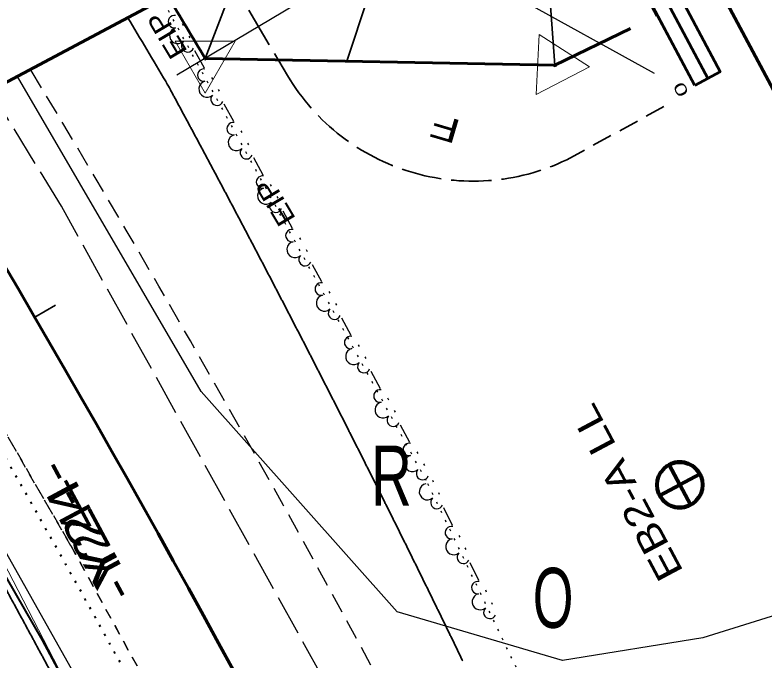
# Model space of a CAD drawing. Extents: x 2402199 to 2404507, y 568050 to 571478.
# Drawn here: x 2402420.4 to 2402576.7, y 571079.7 to 571214.3 of the extents above; entities that cross this region are included whole.
import ezdxf
from ezdxf.enums import TextEntityAlignment as Align

# ---------------------------------------------------------------- set-up
doc = ezdxf.new("R2010")
doc.units = 0
doc.header["$LTSCALE"] = 1.4
doc.header["$PDMODE"] = 32
doc.header["$PDSIZE"] = 0.7
for name, pattern in [('DOTTED', [1.5, 0.3, -1.2]), ('LONG_DASHED', [7.5, 6, -1.5]), ('MEDIUM_DASHED', [4.5, 3, -1.5]), ('SHORT_DASHED', [2.7, 1.5, -1.2])]:
    doc.linetypes.add(name, pattern=pattern)
for name, color, linetype, lineweight in [('1', 7, 'Continuous', 35), ('11', 7, 'Continuous', 25), ('15', 7, 'DOTTED', 40), ('17', 7, 'MEDIUM_DASHED', 35), ('18', 7, 'SHORT_DASHED', 25), ('19', 7, 'Continuous', 35), ('21', 7, 'Continuous', 40), ('27', 7, 'Continuous', 80), ('28', 7, 'Continuous', 25), ('3', 7, 'Continuous', 25), ('4', 7, 'Continuous', 13), ('52', 7, 'Continuous', 25), ('6', 7, 'Continuous', 35), ('62', 7, 'Continuous', 60), ('63', 7, 'Continuous', 35), ('9', 7, 'Continuous', 13)]:
    doc.layers.add(name, color=color, linetype=linetype, lineweight=lineweight)
doc.layers.add('14', color=7, linetype='Continuous')
doc.layers.add('23', color=7, linetype='Continuous')

msp = doc.modelspace()

# ---------------------------------------------------------------- linework, layer by layer
at = {"layer": '1'}
msp.add_arc((2399929.798, 569697.989), 2935.633, 30.78279, 31.08702, dxfattribs=at)
for points in [[(2402483.513, 571140.326), (2402483.095, 571141.14), (2402482.672, 571141.963), (2402482.255, 571142.777), (2402481.837, 571143.591), (2402481.418, 571144.405), (2402480.999, 571145.218), (2402480.581, 571146.032), (2402480.161, 571146.845), (2402479.742, 571147.659), (2402479.322, 571148.471), (2402478.902, 571149.285), (2402478.482, 571150.098), (2402478.056, 571150.92), (2402477.635, 571151.732), (2402477.215, 571152.544), (2402476.794, 571153.357), (2402476.372, 571154.169), (2402475.95, 571154.981), (2402475.528, 571155.794), (2402475.106, 571156.606), (2402474.683, 571157.417), (2402474.26, 571158.229), (2402473.837, 571159.041), (2402473.413, 571159.853), (2402472.985, 571160.673), (2402472.561, 571161.484), (2402472.137, 571162.295), (2402471.713, 571163.106), (2402471.288, 571163.917), (2402470.863, 571164.728), (2402470.438, 571165.539), (2402470.012, 571166.349), (2402469.587, 571167.159), (2402469.161, 571167.97), (2402468.735, 571168.78), (2402468.303, 571169.599), (2402467.876, 571170.409), (2402467.45, 571171.218), (2402467.022, 571172.028), (2402466.595, 571172.837), (2402466.167, 571173.647), (2402465.739, 571174.456), (2402465.311, 571175.265), (2402464.882, 571176.074), (2402464.453, 571176.883), (2402464.024, 571177.693), (2402463.59, 571178.51), (2402463.16, 571179.318), (2402462.731, 571180.126), (2402462.3, 571180.935), (2402461.87, 571181.743), (2402461.439, 571182.551), (2402461.009, 571183.358), (2402460.578, 571184.167), (2402460.146, 571184.974), (2402459.714, 571185.782), (2402459.282, 571186.59), (2402458.845, 571187.405), (2402458.413, 571188.213), (2402457.98, 571189.02), (2402457.547, 571189.826), (2402457.114, 571190.633), (2402456.681, 571191.44), (2402456.247, 571192.247), (2402455.813, 571193.053), (2402455.379, 571193.859), (2402454.945, 571194.666), (2402454.509, 571195.472), (2402454.07, 571196.286), (2402453.635, 571197.092), (2402453.199, 571197.897), (2402452.763, 571198.703), (2402451.891, 571200.313)], [(2402513.706, 571079.688), (2402513.308, 571080.51), (2402512.909, 571081.333), (2402512.511, 571082.156), (2402512.112, 571082.978), (2402511.713, 571083.801), (2402511.314, 571084.623), (2402510.914, 571085.446), (2402510.514, 571086.268), (2402510.113, 571087.091), (2402509.708, 571087.921), (2402509.308, 571088.743), (2402508.907, 571089.564), (2402508.505, 571090.386), (2402508.104, 571091.207), (2402507.703, 571092.029), (2402507.3, 571092.85), (2402506.898, 571093.671), (2402506.496, 571094.492), (2402506.093, 571095.313), (2402505.689, 571096.134), (2402505.281, 571096.964), (2402504.878, 571097.784), (2402504.474, 571098.604), (2402504.07, 571099.424), (2402503.666, 571100.245), (2402503.261, 571101.064), (2402502.856, 571101.884), (2402502.451, 571102.704), (2402502.046, 571103.524), (2402501.64, 571104.344), (2402501.234, 571105.164), (2402500.823, 571105.992), (2402500.416, 571106.811), (2402500.01, 571107.63), (2402499.603, 571108.449), (2402499.195, 571109.268), (2402498.788, 571110.086), (2402498.38, 571110.905), (2402497.972, 571111.724), (2402497.564, 571112.542), (2402497.155, 571113.361), (2402496.746, 571114.179), (2402496.333, 571115.006), (2402495.924, 571115.824), (2402495.514, 571116.642), (2402495.104, 571117.459), (2402494.694, 571118.277), (2402494.284, 571119.094), (2402493.873, 571119.912), (2402493.462, 571120.729), (2402493.051, 571121.547), (2402492.64, 571122.363), (2402492.228, 571123.181), (2402491.811, 571124.006), (2402491.399, 571124.823), (2402490.986, 571125.639), (2402490.574, 571126.456), (2402490.161, 571127.272), (2402489.748, 571128.088), (2402489.334, 571128.904), (2402488.92, 571129.72), (2402488.506, 571130.536), (2402488.092, 571131.351), (2402487.677, 571132.167), (2402487.257, 571132.992), (2402486.842, 571133.807), (2402486.427, 571134.622), (2402486.012, 571135.437), (2402485.596, 571136.252), (2402485.18, 571137.067), (2402484.763, 571137.882), (2402484.347, 571138.696), (2402483.93, 571139.511), (2402483.513, 571140.325)], [(2402513.706, 571079.688), (2402513.308, 571080.51), (2402512.909, 571081.333), (2402512.511, 571082.156), (2402512.112, 571082.978), (2402511.713, 571083.801), (2402511.314, 571084.623), (2402510.914, 571085.446), (2402510.514, 571086.268), (2402510.113, 571087.091), (2402509.708, 571087.921), (2402509.308, 571088.743), (2402508.907, 571089.564), (2402508.505, 571090.386), (2402508.104, 571091.207), (2402507.703, 571092.029), (2402507.3, 571092.85), (2402506.898, 571093.671), (2402506.496, 571094.492), (2402506.093, 571095.313), (2402505.689, 571096.134), (2402505.281, 571096.964), (2402504.878, 571097.784), (2402504.474, 571098.604), (2402504.07, 571099.424), (2402503.666, 571100.245), (2402503.261, 571101.064), (2402502.856, 571101.884), (2402502.451, 571102.704), (2402502.046, 571103.524), (2402501.64, 571104.344), (2402501.234, 571105.164), (2402500.823, 571105.992), (2402500.416, 571106.811), (2402500.01, 571107.63), (2402499.603, 571108.449), (2402499.195, 571109.268), (2402498.788, 571110.086), (2402498.38, 571110.905), (2402497.972, 571111.724), (2402497.564, 571112.542), (2402497.155, 571113.361), (2402496.746, 571114.179), (2402496.333, 571115.006), (2402495.924, 571115.824), (2402495.514, 571116.642), (2402495.104, 571117.459), (2402494.694, 571118.277), (2402494.284, 571119.094), (2402493.873, 571119.912), (2402493.462, 571120.729), (2402493.051, 571121.547), (2402492.64, 571122.363), (2402492.228, 571123.181), (2402491.811, 571124.006), (2402491.399, 571124.823), (2402490.986, 571125.639), (2402490.574, 571126.456), (2402490.161, 571127.272), (2402489.748, 571128.088), (2402489.334, 571128.904), (2402488.92, 571129.72), (2402488.506, 571130.536), (2402488.092, 571131.351), (2402487.677, 571132.167), (2402487.257, 571132.992), (2402486.842, 571133.807), (2402486.427, 571134.622), (2402486.012, 571135.437), (2402485.596, 571136.252), (2402485.18, 571137.067), (2402484.763, 571137.882), (2402484.347, 571138.696), (2402483.93, 571139.511), (2402483.513, 571140.325)], [(2402445.746, 571043.492), (2402445.335, 571044.281), (2402444.925, 571045.069), (2402444.513, 571045.858), (2402444.102, 571046.647), (2402443.691, 571047.436), (2402443.279, 571048.224), (2402442.867, 571049.012), (2402442.454, 571049.8), (2402442.041, 571050.588), (2402441.624, 571051.385), (2402441.211, 571052.172), (2402440.797, 571052.96), (2402440.384, 571053.748), (2402439.97, 571054.535), (2402439.556, 571055.322), (2402439.142, 571056.109), (2402438.727, 571056.897), (2402438.312, 571057.684), (2402437.897, 571058.47), (2402437.482, 571059.257), (2402437.062, 571060.052), (2402436.646, 571060.838), (2402436.23, 571061.624), (2402435.813, 571062.41), (2402435.397, 571063.196), (2402434.98, 571063.983), (2402434.563, 571064.768), (2402434.146, 571065.554), (2402433.728, 571066.339), (2402433.311, 571067.125), (2402432.893, 571067.91), (2402432.47, 571068.703), (2402432.051, 571069.488), (2402431.632, 571070.273), (2402431.213, 571071.058), (2402430.794, 571071.843), (2402430.374, 571072.627), (2402429.954, 571073.411), (2402429.535, 571074.196), (2402429.114, 571074.98), (2402428.694, 571075.764), (2402428.273, 571076.547), (2402427.848, 571077.34), (2402427.426, 571078.123), (2402427.005, 571078.906), (2402426.583, 571079.69), (2402426.161, 571080.473), (2402425.739, 571081.256), (2402425.316, 571082.039), (2402424.894, 571082.822), (2402424.471, 571083.604), (2402424.047, 571084.387), (2402423.624, 571085.169), (2402423.195, 571085.96), (2402422.771, 571086.742), (2402422.347, 571087.524), (2402421.923, 571088.306), (2402421.498, 571089.088), (2402421.073, 571089.87), (2402420.648, 571090.651), (2402420.223, 571091.432), (2402419.797, 571092.214), (2402419.371, 571092.995), (2402418.945, 571093.775), (2402418.514, 571094.565), (2402418.087, 571095.346), (2402417.66, 571096.126), (2402417.233, 571096.907), (2402416.806, 571097.687), (2402416.378, 571098.467), (2402415.95, 571099.247), (2402415.522, 571100.027), (2402415.094, 571100.807), (2402414.665, 571101.587)]]:
    msp.add_spline(points, degree=3, dxfattribs=at)
at = {"layer": '11', "linetype": 'DOTTED'}
for p, q in [((2402506.107, 571117.3), (2402451.036, 571217.605)), ((2402547.635, 571031.07), (2402506.107, 571117.3))]:
    msp.add_line(p, q, dxfattribs=at)
at = {"layer": '11'}
for p, q in [((2402455.475, 571212.078), (2402455.277, 571212.438)), ((2402456.856, 571209.56), (2402456.66, 571209.919)), ((2402459.853, 571203.252), (2402457.879, 571206.847)), ((2402461.593, 571200.932), (2402461.396, 571201.292)), ((2402462.975, 571198.418), (2402462.777, 571198.777)), ((2402465.971, 571192.108), (2402463.997, 571195.703)), ((2402467.712, 571189.789), (2402467.514, 571190.149)), ((2402469.094, 571187.273), (2402468.896, 571187.633)), ((2402472.089, 571180.964), (2402470.116, 571184.559)), ((2402473.831, 571178.645), (2402473.633, 571179.005)), ((2402475.213, 571176.127), (2402475.016, 571176.487)), ((2402478.208, 571169.821), (2402476.235, 571173.414)), ((2402479.949, 571167.501), (2402479.752, 571167.86)), ((2402481.33, 571164.986), (2402481.132, 571165.345)), ((2402484.327, 571158.676), (2402482.353, 571162.271)), ((2402486.067, 571156.358), (2402485.869, 571156.718)), ((2402487.448, 571153.842), (2402487.251, 571154.201)), ((2402490.445, 571147.532), (2402488.471, 571151.127)), ((2402492.185, 571145.214), (2402491.988, 571145.574)), ((2402493.567, 571142.696), (2402493.371, 571143.056)), ((2402496.564, 571136.388), (2402494.59, 571139.983)), ((2402498.304, 571134.068), (2402498.107, 571134.427)), ((2402499.685, 571131.554), (2402499.488, 571131.913)), ((2402502.682, 571125.244), (2402500.708, 571128.839)), ((2402504.422, 571122.926), (2402504.224, 571123.285)), ((2402505.804, 571120.41), (2402505.606, 571120.769)), ((2402507.64, 571116.955), (2402507.462, 571117.324)), ((2402508.885, 571114.368), (2402508.707, 571114.738)), ((2402511.54, 571107.91), (2402509.761, 571111.605)), ((2402513.155, 571105.503), (2402512.977, 571105.872)), ((2402514.402, 571102.913), (2402514.224, 571103.283)), ((2402517.056, 571096.456), (2402515.277, 571100.151)), ((2402518.671, 571094.049), (2402518.493, 571094.418)), ((2402519.917, 571091.46), (2402519.74, 571091.83))]:
    msp.add_line(p, q, dxfattribs=at)
for centre, radius, start, end in [((2402453.607, 571212.923), 1.297, 79.53681, 280.33338), ((2402454.27, 571210.012), 1.691, 104.73209, 312.80458), ((2402456.37, 571207.891), 1.297, 137.20328, 337.99985), ((2402459.725, 571201.779), 1.297, 79.53681, 280.33338), ((2402460.388, 571198.868), 1.691, 104.73209, 312.80458), ((2402462.489, 571196.746), 1.297, 137.20328, 337.99985), ((2402465.844, 571190.635), 1.297, 79.53681, 280.33338), ((2402466.507, 571187.724), 1.691, 104.73209, 312.80458), ((2402468.607, 571185.602), 1.297, 137.20328, 337.99985), ((2402471.962, 571179.491), 1.297, 79.53681, 280.33338), ((2402472.625, 571176.58), 1.691, 104.73209, 312.80458), ((2402474.726, 571174.458), 1.297, 137.20328, 337.99985), ((2402478.081, 571168.347), 1.297, 79.53681, 280.33338), ((2402478.744, 571165.436), 1.691, 104.73209, 312.80458), ((2402480.844, 571163.314), 1.297, 137.20328, 337.99985), ((2402484.199, 571157.203), 1.297, 79.53681, 280.33338), ((2402484.862, 571154.292), 1.691, 104.73209, 312.80458), ((2402486.963, 571152.17), 1.297, 137.20328, 337.99985), ((2402490.318, 571146.059), 1.297, 79.53681, 280.33338), ((2402490.981, 571143.148), 1.691, 104.73209, 312.80458), ((2402493.081, 571141.026), 1.297, 137.20328, 337.99985), ((2402496.436, 571134.915), 1.297, 79.53681, 280.33338), ((2402497.099, 571132.004), 1.691, 104.73209, 312.80458), ((2402499.2, 571129.882), 1.297, 137.20328, 337.99985), ((2402502.555, 571123.771), 1.297, 79.53681, 280.33338), ((2402503.217, 571120.86), 1.691, 104.73209, 312.80458), ((2402505.318, 571118.738), 1.297, 137.20328, 337.99985), ((2402506.325, 571114.958), 1.691, 101.67853, 309.75102), ((2402508.31, 571112.727), 1.297, 134.14972, 334.94629), ((2402511.335, 571106.446), 1.297, 76.48325, 277.27982), ((2402511.841, 571103.503), 1.691, 101.67853, 309.75102), ((2402513.826, 571101.273), 1.297, 134.14972, 334.94629), ((2402516.851, 571094.992), 1.297, 76.48325, 277.27982), ((2402517.358, 571092.049), 1.691, 101.67853, 309.75102), ((2402519.342, 571089.819), 1.297, 134.14972, 334.94629)]:
    msp.add_arc(centre, radius, start, end, dxfattribs=at)
at = {"layer": '15'}
msp.add_arc((2399911.332, 569690.208), 2887.133, 22.84472, 37.57762, dxfattribs=at)
at = {"layer": '17', "linetype": 'LONG_DASHED'}
msp.add_line((2402463.715, 571224.347), (2402477.172, 571201.701), dxfattribs=at)
at = {"layer": '17', "linetype": 'Continuous', "lineweight": 60}
for p, q in [((2402548.672, 571211.487), (2402532.935, 571203.827)), ((2402532.935, 571203.827), (2402460.002, 571205.264))]:
    msp.add_line(p, q, dxfattribs=at)
at = {"layer": '17'}
msp.add_line((2402535.371, 571184.14), (2402556.949, 571195.919), dxfattribs=at)
at = {"layer": '17', "linetype": 'Continuous', "lineweight": 60}
msp.add_arc((2399929.798, 569697.989), 2945.133, 30.78279, 31.07706, dxfattribs=at)
at = {"layer": '17', "lineweight": 25}
msp.add_arc((2399953.615, 569708.021), 2887.133, 22.84472, 31.18511, dxfattribs=at)
at = {"layer": '17', "linetype": 'LONG_DASHED'}
msp.add_arc((2402515.857, 571224.689), 45, 210.71926, 295.69882, dxfattribs=at)
at = {"layer": '18'}
for points in [[(2402365.587, 571157.036), (2402392.015, 571170.595), (2402409.404, 571142.738), (2402432.028, 571103.686), (2402454.91, 571062.094), (2402476.431, 571020.802)], [(2402476.431, 571020.802), (2402454.91, 571062.094), (2402432.028, 571103.686), (2402409.404, 571142.738), (2402392.015, 571170.595), (2402365.587, 571157.036)]]:
    msp.add_lwpolyline(points, dxfattribs=at)
at = {"layer": '19'}
for p, q in [((2402532.935, 571203.827), (2402529.783, 571247.012)), ((2402460.002, 571205.264), (2402468.245, 571226.755))]:
    msp.add_line(p, q, dxfattribs=at)
at = {"layer": '19', "linetype": 'LONG_DASHED', "lineweight": 25}
msp.add_lwpolyline([(2402553.96, 570938.781), (2402489.547, 571067.152), (2402430.056, 571174.439), (2402385.495, 571247.202)], dxfattribs=at)
at = {"layer": '21'}
msp.add_lwpolyline([(2402571.932, 570780.533), (2402538.299, 570859.007), (2402503.143, 570934.851), (2402464.804, 571011.777), (2402426.113, 571084.024), (2402384.214, 571156.832), (2402372.534, 571175.865)], dxfattribs=at)
at = {"layer": '27'}
for p, q in [((2402556.729, 571120.585), (2402561.183, 571112.209)), ((2402563.144, 571118.624), (2402554.768, 571114.172)), ((2402554.743, 571114.218), (2402554.768, 571114.172))]:
    msp.add_line(p, q, dxfattribs=at)
for points in [[(2402563.144, 571118.624), (2402558.955, 571116.398), (2402556.729, 571120.585), (2402556.683, 571120.56)], [(2402554.768, 571114.172), (2402558.955, 571116.398), (2402561.183, 571112.209)]]:
    msp.add_lwpolyline(points, dxfattribs=at)
msp.add_circle((2402558.956, 571116.397), 4.743, dxfattribs=at)
for start, end in [(28, 118.64427), (207.35574, 298)]:
    msp.add_arc((2402558.956, 571116.397), 4.743, start, end, dxfattribs=at)
at = {"layer": '28'}
for points in [[(2402608.658, 571102.353), (2402586.696, 571091.641), (2402563.737, 571084.481), (2402534.511, 571079.781), (2402500.05, 571089.933), (2402459.199, 571135.878), (2402421.36, 571200.686), (2402420.824, 571201.541)], [(2402374.812, 571177.076), (2402399.705, 571135.603), (2402440.232, 571063.522), (2402479.967, 570987.625), (2402515.512, 570914.776), (2402552.113, 570833.795), (2402574.37, 570781.072)]]:
    msp.add_lwpolyline(points, dxfattribs=at)
at = {"layer": '3'}
for points in [[(2402603.164, 571099.846), (2402586.696, 571091.641), (2402563.737, 571084.481), (2402534.511, 571079.781), (2402500.05, 571089.933), (2402459.199, 571135.878), (2402421.36, 571200.686), (2402420.824, 571201.541)], [(2402374.812, 571177.076), (2402399.705, 571135.603), (2402440.232, 571063.522), (2402479.967, 570987.625), (2402515.512, 570914.776), (2402552.113, 570833.795), (2402574.37, 570781.072)]]:
    msp.add_lwpolyline(points, dxfattribs=at)
at = {"layer": '4', "lineweight": 35}
msp.add_line((2402542.396, 571236.363), (2402554.121, 571214.041), dxfattribs=at)
at = {"layer": '52'}
msp.add_line((2402553.666, 571202.093), (2402489.124, 571237.857), dxfattribs=at)
at = {"layer": '6'}
for p, q in [((2402489.56, 571204.682), (2402502.996, 571245.233)), ((2402424.462, 571151.326), (2402428.783, 571153.843))]:
    msp.add_line(p, q, dxfattribs=at)
at = {"layer": '6', "lineweight": 13}
msp.add_line((2402415.453, 571105.055), (2402511.71, 570919.872), dxfattribs=at)
at = {"layer": '62'}
msp.add_arc((2399929.798, 569697.989), 2887.133, 22.84477, 31.13893, dxfattribs=at)
at = {"layer": '63', "lineweight": 60}
msp.add_line((2402531.138, 571287.671), (2402757.403, 570862.128), dxfattribs=at)
at = {"layer": '63', "lineweight": 25}
msp.add_line((2402529.855, 571246.876), (2402454.128, 571201.765), dxfattribs=at)
at = {"layer": '63', "lineweight": 60}
msp.add_lwpolyline([(2402542.527, 571266.252), (2402277.643, 571125.41), (2402266.253, 571146.83), (2402531.138, 571287.671)], close=True, dxfattribs=at)
at = {"layer": '63', "lineweight": 53}
for points in [[(2402562.117, 571199.632), (2402533.948, 571252.609), (2402539.222, 571255.413), (2402567.39, 571202.436)], [(2402562.117, 571199.632), (2402548.081, 571226.03), (2402550.746, 571227.448), (2402564.783, 571201.049)]]:
    msp.add_lwpolyline(points, close=True, dxfattribs=at)
at = {"layer": '9'}
for points in [[(2402540.138, 571203.476), (2402529.041, 571197.768), (2402529.621, 571210.233)], [(2402459.971, 571198.052), (2402453.776, 571208.884), (2402466.254, 571208.859)]]:
    msp.add_lwpolyline(points, close=True, dxfattribs=at)
for p in [(2402460, 571205.265), (2402532.933, 571203.825)]:
    msp.add_point(p, dxfattribs=at)

# ---------------------------------------------------------------- texts
at = {"layer": '14', "width": 1.2}
for p in [(2402453.773, 571211.146), (2402476.342, 571176.297)]:
    msp.add_text('EIP', height=4, rotation=120.856, dxfattribs=at).set_placement(p, align=Align.CENTER)
at = {"layer": '14', "width": 0.7}
msp.add_text('R', height=12.5, dxfattribs=at).set_placement((2402498.842, 571112.08), align=Align.CENTER)
at = {"layer": '17', "width": 1.45}
msp.add_text('F', height=5, rotation=163.601, dxfattribs=at).set_placement((2402510.749, 571193.054), align=Align.CENTER)
at = {"layer": '23', "width": 1.1}
msp.add_text('CRESCENT ROAD (R-2719BA)', height=3, rotation=205.547, dxfattribs=at).set_placement((2402599.838, 571083.818), align=Align.CENTER)
at = {"layer": '27', "width": 1.25}
msp.add_text('EB2-A LL', height=5.625, rotation=118, dxfattribs=at).set_placement((2402550.366, 571116.084), align=Align.CENTER)
at = {"layer": '4', "width": 1.1}
msp.add_text('-Y24-', height=7, rotation=118.248, dxfattribs=at).set_placement((2402439.446, 571105.41), align=Align.CENTER)
at = {"layer": '63'}
for s, height, rotation, width, p in [('0', 2.399, 118, 1.65, (2402560.242, 571199.351)), ('-Y24-', 7, 118.248, 1.4, (2402437.901, 571108.286))]:
    msp.add_text(s, height=height, rotation=rotation, dxfattribs=dict(at, width=width)).set_placement(p, align=Align.CENTER)
at = {"layer": '9', "width": 0.65}
msp.add_text('O', height=12.5, dxfattribs=at).set_placement((2402532.543, 571086.596), align=Align.CENTER)

doc.saveas('drawing.dxf')
